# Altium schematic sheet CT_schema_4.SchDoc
size 221 x 258 mm
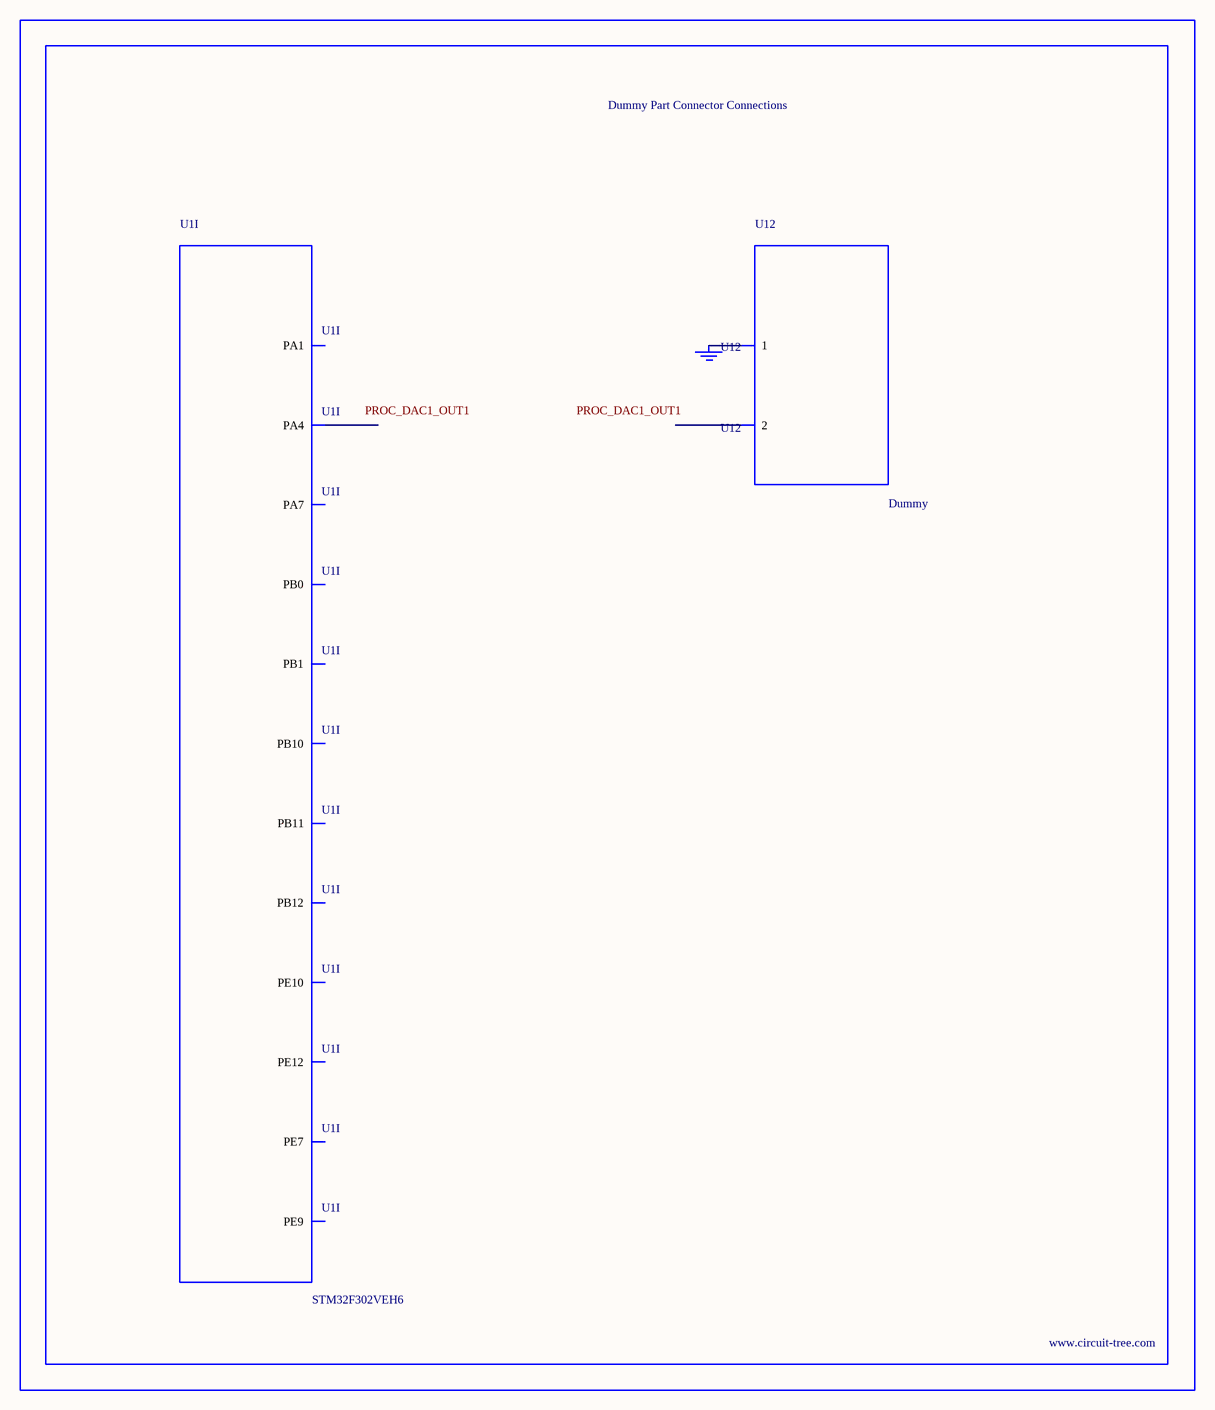
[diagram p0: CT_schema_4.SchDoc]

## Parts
BORDER3  (no value)
GND_INSTANCE_3_0  (no value)
U1  STM32F302VEH6  [UFBGA100]  (part I of 9)
U12  Dummy  [DUMMY_PACKAGE_112]

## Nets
NetGND_INSTANCE_3_0_0: GND_INSTANCE_3_0.0(GND) U12.1

Not connected (* = marked no-connect by the designer): U1 L8(PE10) L9(PE12) L10(PB10) L11(PB11) L12(PB12) M2(PA1) M3(PA4) M4(PA7) M5(PB0) M6(PB1) M7(PE7) M8(PE9); U12 2

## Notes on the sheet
- Labels drawn without touching a wire or pin: PROC_DAC1_OUT1

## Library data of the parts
BORDER3 = BORDER_PAGE3
GND_INSTANCE_3_0 = GND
